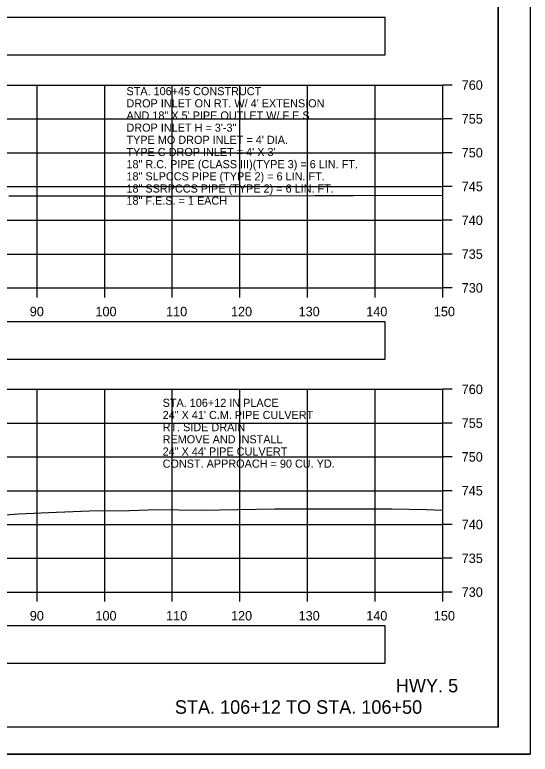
# Model space of a CAD drawing. Extents: x 1202951 to 1376887, y 378065 to 728038.
# Drawn here: x 1376671.4 to 1376747.6, y 379687.9 to 379797.2 of the extents above; entities that cross this region are included whole.
import ezdxf

# ---------------------------------------------------------------- set-up
doc = ezdxf.new("R2010")
doc.units = 0
for name, color, linetype in [('R_Alt Surface', 7, 'Continuous'), ('R_Axis', 7, 'Continuous'), ('R_Axis Annot', 7, 'Continuous'), ('R_Border', 7, 'Continuous'), ('R_Draft', 7, 'Continuous'), ('R_Exist Surface', 7, 'Continuous'), ('R_Grid', 7, 'Continuous'), ('R_No Plot', 7, 'Continuous'), ('R_Water Annot', 7, 'Continuous')]:
    doc.layers.add(name, color=color, linetype=linetype)

msp = doc.modelspace()

# ---------------------------------------------------------------- linework, layer by layer
at = {"layer": 'R_Alt Surface'}
for points in [[(1376615.43, 379791.32), (1376726.14, 379791.32), (1376726.14, 379796.84), (1376615.43, 379796.84)], [(1376615.43, 379746.32), (1376726.14, 379746.32), (1376726.14, 379751.84), (1376615.43, 379751.84)], [(1376615.43, 379701.32), (1376726.14, 379701.32), (1376726.14, 379706.84), (1376615.43, 379706.84)]]:
    msp.add_lwpolyline(points, close=True, dxfattribs=at)
at = {"layer": 'R_Axis'}
for p, q in [((1376734.67, 379756.84), (1376734.67, 379786.84)), ((1376736.07, 379786.84), (1376734.67, 379786.84)), ((1376736.07, 379781.84), (1376734.67, 379781.84)), ((1376736.07, 379776.84), (1376734.67, 379776.84)), ((1376736.07, 379771.84), (1376734.67, 379771.84)), ((1376736.07, 379766.84), (1376734.67, 379766.84)), ((1376736.07, 379761.84), (1376734.67, 379761.84)), ((1376434.67, 379756.84), (1376734.67, 379756.84)), ((1376674.67, 379755.44), (1376674.67, 379756.84)), ((1376684.67, 379755.44), (1376684.67, 379756.84)), ((1376694.67, 379755.44), (1376694.67, 379756.84)), ((1376704.67, 379755.44), (1376704.67, 379756.84)), ((1376714.67, 379755.44), (1376714.67, 379756.84)), ((1376724.67, 379755.44), (1376724.67, 379756.84)), ((1376734.67, 379755.44), (1376734.67, 379756.84)), ((1376736.07, 379756.84), (1376734.67, 379756.84)), ((1376734.67, 379711.84), (1376734.67, 379741.84)), ((1376736.07, 379741.84), (1376734.67, 379741.84)), ((1376736.07, 379736.84), (1376734.67, 379736.84)), ((1376736.07, 379731.84), (1376734.67, 379731.84)), ((1376736.07, 379726.84), (1376734.67, 379726.84)), ((1376736.07, 379721.84), (1376734.67, 379721.84)), ((1376736.07, 379716.84), (1376734.67, 379716.84)), ((1376434.67, 379711.84), (1376734.67, 379711.84)), ((1376674.67, 379710.44), (1376674.67, 379711.84)), ((1376684.67, 379710.44), (1376684.67, 379711.84)), ((1376694.67, 379710.44), (1376694.67, 379711.84)), ((1376704.67, 379710.44), (1376704.67, 379711.84)), ((1376714.67, 379710.44), (1376714.67, 379711.84)), ((1376724.67, 379710.44), (1376724.67, 379711.84)), ((1376734.67, 379710.44), (1376734.67, 379711.84)), ((1376736.07, 379711.84), (1376734.67, 379711.84))]:
    msp.add_line(p, q, dxfattribs=at)
at = {"layer": 'R_Border'}
for q in [(1376742.85, 379897.3), (1376426.67, 379691.84)]:
    msp.add_line((1376742.85, 379691.84), q, dxfattribs=at)
at = {"layer": 'R_Exist Surface'}
for points in [[(1376670.5, 379770.47), (1376681.4, 379770.45), (1376689.73, 379770.45), (1376701.41, 379770.4), (1376715.73, 379770.51), (1376721.42, 379770.48), (1376734.67, 379770.56)], [(1376668.02, 379723.14), (1376671.93, 379723.43), (1376677.54, 379723.67), (1376682.4, 379723.87), (1376688.33, 379723.91), (1376692.5, 379724.06), (1376698.9, 379723.98), (1376709.83, 379724.15), (1376727.15, 379724.17), (1376732.21, 379724.06), (1376734.67, 379723.96)]]:
    msp.add_lwpolyline(points, dxfattribs=at)
at = {"layer": 'R_Grid'}
for p, q in [((1376434.67, 379786.84), (1376734.67, 379786.84)), ((1376674.67, 379756.84), (1376674.67, 379786.84)), ((1376684.67, 379756.84), (1376684.67, 379786.84)), ((1376694.67, 379756.84), (1376694.67, 379786.84)), ((1376704.67, 379756.84), (1376704.67, 379786.84)), ((1376714.67, 379756.84), (1376714.67, 379786.84)), ((1376724.67, 379756.84), (1376724.67, 379786.84)), ((1376734.67, 379756.84), (1376734.67, 379786.84)), ((1376434.67, 379781.84), (1376734.67, 379781.84)), ((1376434.67, 379776.84), (1376734.67, 379776.84)), ((1376434.67, 379771.84), (1376734.67, 379771.84)), ((1376434.67, 379766.84), (1376734.67, 379766.84)), ((1376434.67, 379761.84), (1376734.67, 379761.84)), ((1376434.67, 379756.84), (1376734.67, 379756.84)), ((1376434.67, 379741.84), (1376734.67, 379741.84)), ((1376674.67, 379711.84), (1376674.67, 379741.84)), ((1376684.67, 379711.84), (1376684.67, 379741.84)), ((1376694.67, 379711.84), (1376694.67, 379741.84)), ((1376704.67, 379711.84), (1376704.67, 379741.84)), ((1376714.67, 379711.84), (1376714.67, 379741.84)), ((1376724.67, 379711.84), (1376724.67, 379741.84)), ((1376734.67, 379711.84), (1376734.67, 379741.84)), ((1376434.67, 379736.84), (1376734.67, 379736.84)), ((1376434.67, 379731.84), (1376734.67, 379731.84)), ((1376434.67, 379726.84), (1376734.67, 379726.84)), ((1376434.67, 379721.84), (1376734.67, 379721.84)), ((1376434.67, 379716.84), (1376734.67, 379716.84)), ((1376434.67, 379711.84), (1376734.67, 379711.84))]:
    msp.add_line(p, q, dxfattribs=at)
at = {"layer": 'R_No Plot'}
msp.add_line((1376414.27, 379687.87), (1376747.6, 379687.87), dxfattribs=at)
for points in [[(1376414.26, 379901.2), (1376747.6, 379901.2), (1376747.6, 379687.86), (1376414.26, 379687.86)], [(1376660.59, 379897.3), (1376680.21, 379897.3), (1376680.21, 379887.42), (1376696.32, 379887.42), (1376719.52, 379887.42), (1376719.64, 379859.27), (1376742.85, 379859.27), (1376742.85, 379691.84), (1376426.67, 379691.84), (1376426.67, 379897.3)]]:
    msp.add_lwpolyline(points, close=True, dxfattribs=at)

# ---------------------------------------------------------------- texts
at = {"layer": 'R_Axis Annot'}
for s, p in [('760', (1376737.47, 379786.14)), ('755', (1376737.47, 379781.14)), ('750', (1376737.47, 379776.14)), ('745', (1376737.47, 379771.14)), ('740', (1376737.47, 379766.14)), ('735', (1376737.47, 379761.14)), ('730', (1376737.47, 379756.14)), ('90', (1376673.59, 379752.64)), ('100', (1376683.3, 379752.64)), ('110', (1376693.75, 379752.64)), ('120', (1376703.35, 379752.64)), ('130', (1376713.35, 379752.64)), ('140', (1376723.35, 379752.64)), ('150', (1376733.35, 379752.64)), ('760', (1376737.47, 379741.14)), ('755', (1376737.47, 379736.14)), ('750', (1376737.47, 379731.14)), ('745', (1376737.47, 379726.14)), ('740', (1376737.47, 379721.14)), ('735', (1376737.47, 379716.14)), ('730', (1376737.47, 379711.14)), ('90', (1376673.59, 379707.64)), ('100', (1376683.3, 379707.64)), ('110', (1376693.75, 379707.64)), ('120', (1376703.35, 379707.64)), ('130', (1376713.35, 379707.64)), ('140', (1376723.35, 379707.64)), ('150', (1376733.35, 379707.64))]:
    msp.add_text(s, height=1.4, dxfattribs=at).set_placement(p)
at = {"layer": 'R_Draft'}
for s, p in [('HWY. 5', (1376727.73, 379697.01)), ('STA. 106+12 TO STA. 106+50', (1376695.05, 379693.84))]:
    msp.add_text(s, height=2, dxfattribs=at).set_placement(p)
at = {"layer": 'R_Water Annot'}
for s, p in [('STA. 106+45 CONSTRUCT', (1376687.89, 379785.34)), ("DROP INLET ON RT. W/ 4' EXTENSION", (1376687.89, 379783.54)), ('AND 18" X 5\' PIPE OUTLET W/ F.E.S. ', (1376687.89, 379781.74)), ('DROP INLET H = 3\'-3"', (1376687.89, 379779.94)), ("TYPE MO DROP INLET = 4' DIA.", (1376687.89, 379778.14)), ("TYPE C DROP INLET = 4' X 3' ", (1376687.89, 379776.34)), ('18" R.C. PIPE (CLASS III)(TYPE 3) = 6 LIN. FT.', (1376687.89, 379774.54)), ('18" SLPCCS PIPE (TYPE 2) = 6 LIN. FT.', (1376687.89, 379772.74)), ('18" SSRPCCS PIPE (TYPE 2) = 6 LIN. FT.', (1376687.89, 379770.94)), ('18" F.E.S. = 1 EACH', (1376687.89, 379769.14)), ('STA. 106+12 IN PLACE', (1376693.24, 379739.24)), ('24" X 41\' C.M. PIPE CULVERT', (1376693.24, 379737.44)), ('RT. SIDE DRAIN', (1376693.24, 379735.64)), ('REMOVE AND INSTALL', (1376693.24, 379733.84)), ('24" X 44\' PIPE CULVERT', (1376693.24, 379732.04)), ('CONST. APPROACH = 90 CU. YD.', (1376693.24, 379730.24))]:
    msp.add_text(s, height=1.2, dxfattribs=at).set_placement(p)

doc.saveas('drawing.dxf')
